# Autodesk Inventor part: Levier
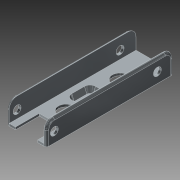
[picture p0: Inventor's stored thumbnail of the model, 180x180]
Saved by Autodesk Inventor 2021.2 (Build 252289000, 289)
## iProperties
Created: 2018-06
Part Number: Levier
Material: Zinc
Document SubType Name: Tôle
Designer: Fabian Perrée
Density: 7 g/cm^3
Appearance: Zinc
Flat Pattern Width: 2.5 cm
Flat Pattern Length: 8 cm
Flat Pattern Area: 20 cm^2
Sheet Metal Rule: Par défaut_mm
Sheet Metal Width: 25,000 mm
Sheet Metal Length: 80,000 mm
Sheet Metal Area: 2000,000 mm^2
Mass: 36.559 g
Surface Area: 77.6202 cm^2
Volume: 5.22272 cm^3
Author: Fabian Perrée
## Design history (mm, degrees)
sketch "Esquisse1"
  geometry: L1 (0, 0)-(-12.5, 0); L2 (-12.5, 0)-(-12.5, 14); L3 (-12.5, 14)-(12.5, 14); L4 (12.5, 14)-(12.5, 0); L5 (12.5, 0)-(0, 0)
  constraints: 10 end point, 3 perpendicular, 1 collinear, 1 horizontal, 1 point on line
  dimensions: "d0" = 12.5 distance of L1.start L1.end; "d1" = 14 distance of L1.end L2.end; "d2" = 25 distance of L2.end L3.end (= 2 x d0)
extrude "Extrusion1" new body sketch "Esquisse1" stored distance "d3" = 80; taper "d4" = 0 deg
feature "Coque1" dims "d5" = 1.5
fillet "Congé1" dims "d6" = 5
sketch "Esquisse2" dims "d19" = 118 deg
  geometry: L1 (22, -80)-(0, -80) reference; L2 (4, -80)-(18, -80); L3 (18, -80)-(18, -65); L4 (18, -65)-(4, -65); L5 (4, -65)-(4, -80); L6 (11, -40)-(11, -80); L7 (7, -46)-(15, -46); L8 (17, -44)-(17, -36); L9 (15, -34)-(7, -34); L10 (5, -36)-(5, -44); L11 (3.5, -44)-(3.5, -36); L12 (7, -32.5)-(15, -32.5); L13 (18.5, -36)-(18.5, -44); L14 (15, -47.5)-(7, -47.5); L15 (15, -31.5)-(7, -31.5); L16 (2.5, -36)-(2.5, -44); L17 (7, -48.5)-(15, -48.5); L18 (19.5, -44)-(19.5, -36); A1 r 2 centre (7, -44) between (5, -44) and (7, -46); A2 r 2 centre (7, -36) between (7, -34) and (5, -36); A3 r 2 centre (15, -36) between (17, -36) and (15, -34); A4 r 2 centre (15, -44) between (15, -46) and (17, -44); A5 r 3.5 centre (7, -36) between (7, -32.5) and (3.5, -36); A6 r 3.5 centre (15, -36) between (18.5, -36) and (15, -32.5); A7 r 3.5 centre (15, -44) between (15, -47.5) and (18.5, -44); A8 r 3.5 centre (7, -44) between (3.5, -44) and (7, -47.5); A9 r 4.5 centre (7, -36) between (7, -31.5) and (2.5, -36); A10 r 4.5 centre (7, -44) between (2.5, -44) and (7, -48.5); A11 r 4.5 centre (15, -44) between (15, -48.5) and (19.5, -44); A12 r 4.5 centre (15, -36) between (19.5, -36) and (15, -31.5); 4 further points
  constraints: 34 end point, 24 point on circle, 12 centre point, 8 parallel, 8 tangent, 7 point on line, 5 perpendicular, 3 equal radius, 2 horizontal, 1 midpoint, 1 vertical, 15 other
  dimensions: "d7" = 14 distance of L3.end L4.end; "d8" = 15 distance of L4.end L2.start; "d21" = 30 distance of point (11, -55) point (11, -25); "d22" = 25 distance from line of L1 point (11, -55); "d23" = 12 distance of point (5, -34) point (5, -46); "d24" = 46 distance between parallel lines of L1 L9; "d25" = 2 radius of A1 (derived); "d26" = 1.5 distance between parallel lines of L10 L11; "d57" = 1 distance between parallel lines of L12 L15
extrude "Extrusion2" cut sketch "Esquisse2" extent not by distance; stored distance "d9" = 80; taper "d10" = 0 deg
sketch "Esquisse3"
  geometry: L1 (0, 0)-(0, 9) reference; L2 (0, 0)-(80, 0) reference; 3 further points
  constraints: 1 horizontal alignment
  dimensions: "d11" = 5 distance from line of L1 point (5, 6.5); "d12" = 6.5 distance from line of L2 point (5, 6.5); "d20" = 65 distance of point (5, 6.5) point (70, 6.5)
hole "Perçage1" sketch "Esquisse3" at (5, 6.5), (70, 6.5) diameter "d13" = 5; stored, may be unused: countersink angle "d17" = 90 deg, drill point angle "d19" = 118 deg; dims "d14" = 6, "d15" = 4, "d16" = 2, "d18" = 8
node "Plan de construction1"
sketch "Esquisse4"
  geometry: L1 (5, -36)-(5, -44) reference; L2 (15, -34)-(7, -34) reference; L3 (17, -44)-(17, -36) reference; L4 (7, -46)-(15, -46) reference; A1 r 2 centre (7, -36) between (7, -34) and (5, -36) reference; A2 r 2 centre (15, -36) between (17, -36) and (15, -34) reference; A3 r 2 centre (15, -44) between (15, -46) and (17, -44) reference; A4 r 2 centre (7, -44) between (5, -44) and (7, -46) reference; 1 further point
feature "Lissage2" sketch "Esquisse4" dims "d62" = 0, "d63" = 90 deg, "d64" = 0, "d65" = 90 deg
node "Plan de construction2"
sketch "Esquisse5"
  geometry: L1 (5, -36)-(5, -44) reference; L2 (7, -46)-(15, -46) reference; L3 (17, -44)-(17, -36) reference; L4 (15, -34)-(7, -34) reference; L5 (17, -44)-(18.05, -44) reference; A1 r 2 centre (7, -44) between (5, -44) and (7, -46) reference; A2 r 2 centre (15, -36) between (17, -36) and (15, -34) reference; A3 r 2 centre (7, -36) between (7, -34) and (5, -36) reference; A4 r 2 centre (15, -44) between (15, -46) and (17, -44) reference; A5 r 2 centre (15, -44) between (15, -46) and (17, -44); 1 further point
  constraints: 2 point on circle, 1 centre point, 1 tangent
feature "Lissage3" sketch "Esquisse5" dims "d44" = 0, "d45" = 90 deg, "d66" = 0, "d67" = 90 deg
sketch "Esquisse6"
  geometry: L1 (4, -65)-(18, -65) reference; L2 (22, -80)-(18, -80) reference; L3 (0, 0)-(22, 0) reference; L4 (11, 0)-(11, -65); 3 further points
  constraints: 2 end point, 2 midpoint, 2 point on line
  dimensions: "d48" = 34 distance of point (11, -21) point (11, -55); "d49" = 25 distance from line of L2 point (11, -55)
hole "Perçage2" sketch "Esquisse6" at (11, -55), (11, -21) diameter "d50" = 10; stored, may be unused: countersink angle "d54" = 90 deg, drill point angle "d56" = 118 deg; dims "d51" = 6, "d52" = 4, "d53" = 2, "d55" = 8
fillet "Congé2" dims "d68" = 1.5
node "Solide1"
feature "Définition1"
other parameters: "d27" = -5, "d43" = 1.5, "d58" = 0.5, "d59" = 2, "d60" = 0, "Epaisseur" = 1.5 (derived), "FacteurX" = 4.4, "RayonPli" = 1.5 (= Epaisseur), "LargeurGrugeage" = 1.5 (= Epaisseur), "ProfondeurGrugeage" = 0.75 (= 0.5 x Epaisseur), "TailleGrugeage" = 6 (= 4 x Epaisseur), "JeuJointure" = 0.01, "RestesMinimum" = 3 (= 2 x Epaisseur), "Rayondetransition" = 1.5 (= RayonPli), "TailleRayonJacobi" = 1.5 (= RayonPli), "TailleJeu" = 1.5 (= Epaisseur), "Epaisseur" = 1.5, "LargeurGrugeage" = 1.5, "ProfondeurGrugeage" = 0.75, "RayonPli" = 1.5, "Rayondetransition" = 1.5, "RestesMinimum" = 3, "TailleGrugeage" = 6, "TailleJeu" = 1.5, "TailleRayonJacobi" = 1.5
